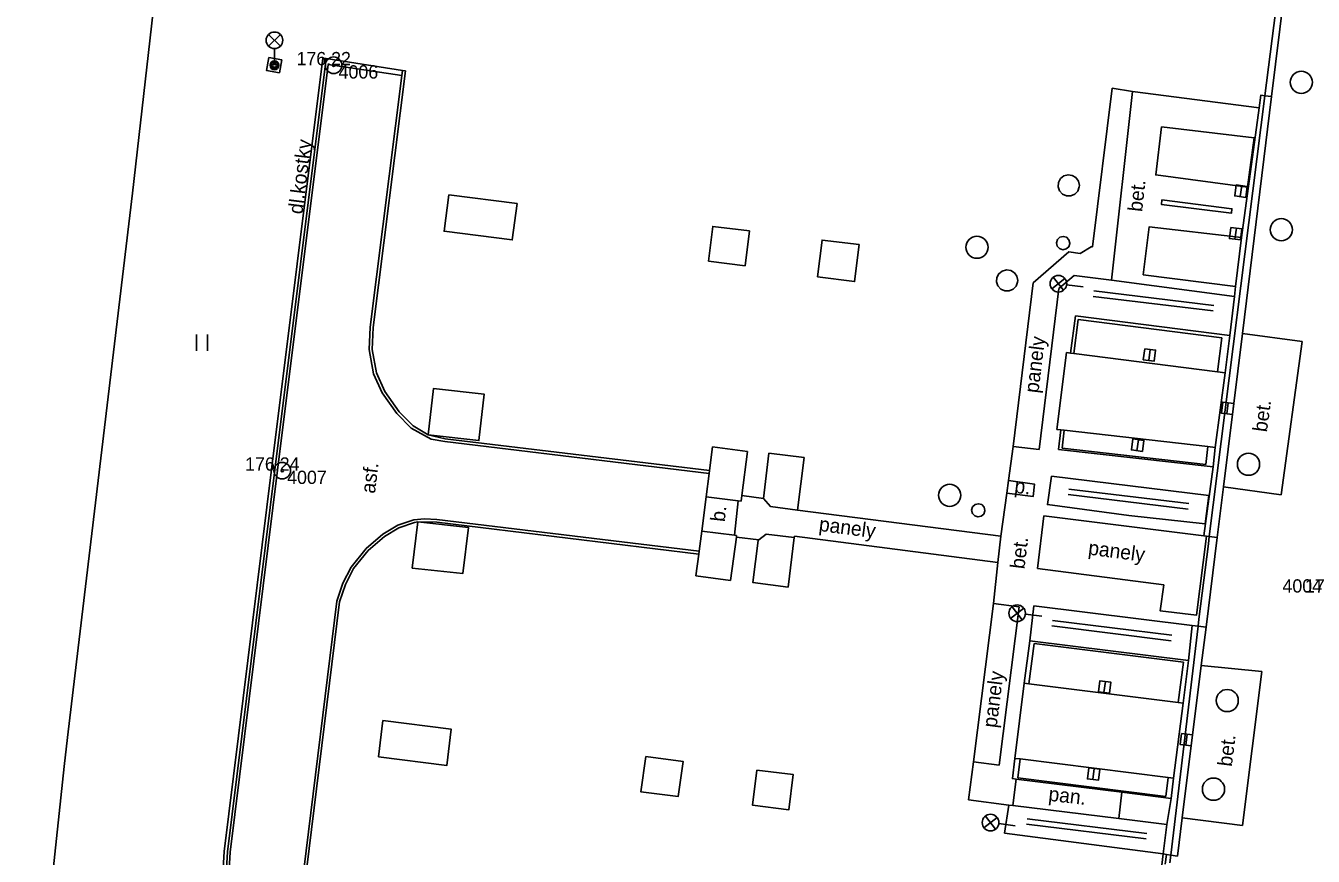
# Model space of a CAD drawing. Extents: x -540235 to -537963, y -1184915 to -1183660.
# Drawn here: x -540189.1 to -540131, y -1184039.7 to -1184002.2 of the extents above; entities that cross this region are included whole.
import ezdxf

# ---------------------------------------------------------------- set-up
doc = ezdxf.new("R2010")
doc.units = 0
for name, color, linetype in [('Vrstva 10', 7, 'Continuous'), ('Vrstva 11', 7, 'Continuous'), ('Vrstva 21', 7, 'Continuous'), ('Vrstva 22', 7, 'Continuous'), ('Vrstva 23', 7, 'Continuous'), ('Vrstva 27', 7, 'Continuous'), ('Vrstva 33', 7, 'Continuous'), ('Vrstva 36', 7, 'Continuous'), ('Vrstva 40', 7, 'Continuous'), ('Vrstva 7', 7, 'Continuous'), ('Vrstva 8', 7, 'Continuous')]:
    doc.layers.add(name, color=color, linetype=linetype)

msp = doc.modelspace()

# ---------------------------------------------------------------- linework, layer by layer
at = {"layer": 'Vrstva 10'}
for p, q in [((-540131.965, -1183998.004), (-540132.877, -1184005.381)), ((-540175.53, -1184003.67), (-540177.84, -1184022.22)), ((-540173.41, -1184015.8), (-540171.95, -1184004.22)), ((-540132.877, -1184005.381), (-540134.197, -1184016.067)), ((-540133.66, -1184007.245), (-540137.85, -1184006.755)), ((-540134.5, -1184013.955), (-540134.24, -1184011.745)), ((-540138.67, -1184013.425), (-540134.5, -1184013.955)), ((-540134.197, -1184016.067), (-540135.053, -1184022.99)), ((-540142.57, -1184020.4), (-540142.13, -1184016.93)), ((-540141.795, -1184016.973), (-540135.315, -1184017.797)), ((-540134.98, -1184017.84), (-540135.42, -1184021.21)), ((-540135.315, -1184017.797), (-540134.98, -1184017.84)), ((-540135.751, -1184021.173), (-540142.239, -1184020.437)), ((-540158.237, -1184022.253), (-540170.16, -1184020.82)), ((-540158.1, -1184021.19), (-540156.522, -1184021.393)), ((-540135.42, -1184021.21), (-540135.751, -1184021.173)), ((-540177.84, -1184022.22), (-540179.98, -1184039.46)), ((-540170.54, -1184024.59), (-540158.718, -1184026.02)), ((-540155.68, -1184025.13), (-540154.41, -1184025.28)), ((-540157.281, -1184027.211), (-540158.85, -1184027)), ((-540176.41, -1184040.28), (-540174.92, -1184028.17)), ((-540136.05, -1184031.055), (-540136.915, -1184037.929)), ((-540144.04, -1184031.85), (-540143.827, -1184031.877)), ((-540143.827, -1184031.877), (-540137.088, -1184032.723)), ((-540137.088, -1184032.723), (-540136.87, -1184032.75)), ((-540137.538, -1184036.1), (-540144.227, -1184035.268)), ((-540136.915, -1184037.929), (-540137.129, -1184039.651)), ((-540137.677, -1184040.019), (-540137.622, -1184039.573))]:
    msp.add_line(p, q, dxfattribs=at)
for points in [[(-540137.85, -1184006.755), (-540138.102, -1184008.917), (-540133.96, -1184009.475), (-540133.66, -1184007.245)], [(-540169.99, -1184009.82), (-540166.915, -1184010.214), (-540167.13, -1184011.85), (-540170.205, -1184011.456), (-540169.99, -1184009.82)], [(-540158.28, -1184012.81), (-540158.085, -1184011.242), (-540156.438, -1184011.447), (-540156.633, -1184013.014), (-540158.28, -1184012.81)], [(-540134.24, -1184011.745), (-540138.395, -1184011.256), (-540138.67, -1184013.425)], [(-540153.36, -1184013.52), (-540153.153, -1184011.854), (-540151.486, -1184012.061), (-540151.693, -1184013.727), (-540153.36, -1184013.52)], [(-540170.16, -1184020.82), (-540170.925, -1184020.636), (-540171.61, -1184020.242), (-540172.24, -1184019.6), (-540172.887, -1184018.684), (-540173.26, -1184017.85), (-540173.451, -1184016.791), (-540173.41, -1184015.8)], [(-540142.13, -1184016.93), (-540141.944, -1184016.954), (-540141.795, -1184016.973)], [(-540170.925, -1184020.636), (-540168.64, -1184020.9), (-540168.395, -1184018.814), (-540170.68, -1184018.55), (-540170.925, -1184020.636)], [(-540142.239, -1184020.437), (-540142.39, -1184020.42), (-540142.57, -1184020.4)], [(-540158.39, -1184023.44), (-540158.254, -1184022.382), (-540158.237, -1184022.253), (-540158.1, -1184021.19)], [(-540156.522, -1184021.393), (-540156.778, -1184023.379), (-540156.81, -1184023.63)], [(-540155.8, -1184023.51), (-540155.551, -1184021.477), (-540153.97, -1184021.67), (-540154.26, -1184024.04)], [(-540135.053, -1184022.99), (-540135.336, -1184025.281), (-540135.836, -1184029.323), (-540136.05, -1184031.055)], [(-540156.81, -1184023.63), (-540156.938, -1184023.615), (-540158.39, -1184023.44)], [(-540154.26, -1184024.04), (-540155.49, -1184023.87), (-540155.8, -1184023.51)], [(-540174.92, -1184028.17), (-540174.661, -1184027.39), (-540174.29, -1184026.68), (-540173.627, -1184025.855), (-540172.89, -1184025.23), (-540172.245, -1184024.84), (-540171.55, -1184024.6), (-540171.397, -1184024.575), (-540170.54, -1184024.59)], [(-540171.65, -1184026.66), (-540171.397, -1184024.575), (-540169.11, -1184024.82), (-540169.363, -1184026.905), (-540171.65, -1184026.66)], [(-540158.85, -1184027), (-540158.718, -1184026.02), (-540158.701, -1184025.891), (-540158.58, -1184024.99)], [(-540158.58, -1184024.99), (-540157.112, -1184025.177), (-540157.01, -1184025.19)], [(-540157.01, -1184025.19), (-540157.019, -1184025.259), (-540157.281, -1184027.211)], [(-540154.41, -1184025.28), (-540154.69, -1184027.51), (-540156.279, -1184027.311), (-540156.04, -1184025.41)], [(-540156.04, -1184025.41), (-540156.008, -1184025.385), (-540155.68, -1184025.13)], [(-540144.227, -1184035.268), (-540144.46, -1184035.24), (-540144.04, -1184031.85)], [(-540136.87, -1184032.75), (-540137.3, -1184036.13), (-540137.538, -1184036.1)], [(-540172.966, -1184033.531), (-540169.89, -1184033.92), (-540170.084, -1184035.559), (-540173.16, -1184035.17), (-540172.966, -1184033.531)], [(-540161.11, -1184035.16), (-540159.424, -1184035.376), (-540159.65, -1184036.96), (-540161.336, -1184036.744), (-540161.11, -1184035.16)], [(-540156.1, -1184035.77), (-540154.455, -1184035.973), (-540154.65, -1184037.56), (-540156.295, -1184037.357), (-540156.1, -1184035.77)], [(-540179.98, -1184039.46), (-540180.085, -1184041.238), (-540179.88, -1184043.51), (-540179.4, -1184045.472), (-540178.64, -1184047.36)], [(-540137.129, -1184039.651), (-540137.425, -1184039.604), (-540137.622, -1184039.573)]]:
    msp.add_lwpolyline(points, dxfattribs=at)
at = {"layer": 'Vrstva 11'}
for p, q in [((-540175.679, -1184003.651), (-540177.989, -1184022.201)), ((-540175.53, -1184003.67), (-540175.679, -1184003.651)), ((-540172.079, -1184004.204), (-540175.53, -1184003.67)), ((-540175.44, -1184003.93), (-540177.719, -1184022.235)), ((-540172.108, -1184004.43), (-540175.44, -1184003.93)), ((-540172.108, -1184004.43), (-540172.079, -1184004.204)), ((-540172.079, -1184004.204), (-540171.95, -1184004.22)), ((-540173.54, -1184015.789), (-540172.108, -1184004.43)), ((-540140.07, -1184005.01), (-540140.96, -1184012.166)), ((-540139.15, -1184005.15), (-540140.107, -1184013.667)), ((-540139.15, -1184005.15), (-540140.07, -1184005.01)), ((-540133.44, -1184005.885), (-540139.15, -1184005.15)), ((-540134.24, -1184011.745), (-540133.44, -1184005.885)), ((-540140.107, -1184013.667), (-540134.55, -1184014.395)), ((-540143.63, -1184013.78), (-540144.53, -1184021.17)), ((-540142.47, -1184014.04), (-540143.36, -1184021.31)), ((-540134.55, -1184014.395), (-540134.5, -1184013.955)), ((-540134.55, -1184014.395), (-540134.761, -1184016.159)), ((-540141.944, -1184016.954), (-540141.73, -1184015.272)), ((-540141.795, -1184016.973), (-540141.6, -1184015.44)), ((-540141.73, -1184015.272), (-540134.761, -1184016.159)), ((-540141.6, -1184015.44), (-540135.12, -1184016.265)), ((-540135.12, -1184016.265), (-540135.315, -1184017.797)), ((-540134.761, -1184016.159), (-540134.98, -1184017.84)), ((-540131.5, -1184016.435), (-540134.197, -1184016.067)), ((-540132.45, -1184023.345), (-540131.5, -1184016.435)), ((-540142.39, -1184020.42), (-540142.49, -1184021.3)), ((-540142.239, -1184020.437), (-540142.33, -1184021.24)), ((-540158.254, -1184022.382), (-540170.179, -1184020.949)), ((-540144.74, -1184022.71), (-540144.53, -1184021.17)), ((-540143.36, -1184021.31), (-540144.53, -1184021.17)), ((-540142.33, -1184021.24), (-540135.842, -1184021.975)), ((-540135.842, -1184021.975), (-540135.751, -1184021.173)), ((-540135.52, -1184022.09), (-540135.42, -1184021.21)), ((-540142.49, -1184021.3), (-540135.52, -1184022.09)), ((-540177.989, -1184022.201), (-540180.129, -1184039.446)), ((-540177.719, -1184022.235), (-540179.859, -1184039.471)), ((-540135.52, -1184022.09), (-540135.929, -1184025.206)), ((-540142.81, -1184022.51), (-540135.713, -1184023.374)), ((-540135.053, -1184022.99), (-540132.45, -1184023.345)), ((-540158.39, -1184023.44), (-540158.58, -1184024.99)), ((-540155.8, -1184023.51), (-540156.778, -1184023.379)), ((-540135.713, -1184023.374), (-540135.87, -1184024.66)), ((-540156.938, -1184023.615), (-540157.112, -1184025.177)), ((-540154.26, -1184024.04), (-540145.1, -1184025.22)), ((-540170.528, -1184024.46), (-540158.701, -1184025.891)), ((-540143.44, -1184026.67), (-540143.15, -1184024.3)), ((-540143.15, -1184024.3), (-540135.929, -1184025.206)), ((-540156.008, -1184025.385), (-540157.019, -1184025.259)), ((-540154.403, -1184025.222), (-540154.41, -1184025.28)), ((-540145.23, -1184026.41), (-540154.403, -1184025.222)), ((-540135.929, -1184025.206), (-540135.82, -1184025.22)), ((-540137.74, -1184027.41), (-540143.44, -1184026.67)), ((-540176.54, -1184040.27), (-540175.047, -1184028.141)), ((-540146.33, -1184035.4), (-540145.43, -1184028.25)), ((-540145.43, -1184028.25), (-540144.27, -1184028.41)), ((-540144.27, -1184028.41), (-540145.17, -1184035.55)), ((-540143.6, -1184028.36), (-540143.79, -1184029.93)), ((-540136.46, -1184029.25), (-540143.6, -1184028.36)), ((-540136.625, -1184030.826), (-540136.46, -1184029.25)), ((-540144.04, -1184031.85), (-540143.79, -1184029.93)), ((-540143.79, -1184029.93), (-540136.625, -1184030.826)), ((-540143.827, -1184031.877), (-540143.59, -1184030.06)), ((-540143.59, -1184030.06), (-540136.857, -1184030.902)), ((-540136.857, -1184030.902), (-540137.088, -1184032.723)), ((-540136.625, -1184030.826), (-540136.87, -1184032.75)), ((-540133.318, -1184031.324), (-540136.05, -1184031.055)), ((-540134.184, -1184038.27), (-540133.318, -1184031.324)), ((-540145.17, -1184035.55), (-540146.33, -1184035.4)), ((-540144.227, -1184035.268), (-540144.33, -1184036.12)), ((-540144.398, -1184036.172), (-540144.55, -1184037.372)), ((-540144.33, -1184036.12), (-540137.647, -1184036.954)), ((-540137.647, -1184036.954), (-540137.538, -1184036.1)), ((-540139.631, -1184036.766), (-540139.768, -1184037.959)), ((-540144.92, -1184038.62), (-540144.73, -1184037.35)), ((-540136.915, -1184037.929), (-540134.184, -1184038.27)), ((-540137.77, -1184039.55), (-540144.92, -1184038.62)), ((-540137.833, -1184040.063), (-540137.77, -1184039.55)), ((-540137.77, -1184039.55), (-540137.622, -1184039.573))]:
    msp.add_line(p, q, dxfattribs=at)
for points in [[(-540178.11, -1184003.62), (-540177.53, -1184003.73), (-540177.64, -1184004.31), (-540178.22, -1184004.2), (-540178.11, -1184003.62)], [(-540132.877, -1184005.381), (-540133.18, -1184005.343), (-540133.366, -1184005.32), (-540133.44, -1184005.885)], [(-540141.55, -1184009.39), (-540141.59, -1184009.199), (-540141.702, -1184009.04), (-540141.868, -1184008.938), (-540142.061, -1184008.911), (-540142.249, -1184008.963), (-540142.401, -1184009.085), (-540142.491, -1184009.258), (-540142.506, -1184009.452), (-540142.442, -1184009.636), (-540142.31, -1184009.78), (-540142.132, -1184009.859), (-540141.937, -1184009.861), (-540141.757, -1184009.785), (-540141.623, -1184009.644), (-540141.555, -1184009.461), (-540141.55, -1184009.39)], [(-540141.98, -1184011.99), (-540142.019, -1184011.841), (-540142.127, -1184011.732), (-540142.275, -1184011.69), (-540142.424, -1184011.727), (-540142.535, -1184011.833), (-540142.58, -1184011.98), (-540142.546, -1184012.129), (-540142.442, -1184012.243), (-540142.296, -1184012.29), (-540142.145, -1184012.258), (-540142.03, -1184012.156), (-540141.981, -1184012.011), (-540141.98, -1184011.99)], [(-540140.96, -1184012.166), (-540141.01, -1184012.16), (-540141.51, -1184012.46), (-540142.02, -1184012.39), (-540143.63, -1184013.78)], [(-540144.33, -1184013.68), (-540144.37, -1184013.489), (-540144.482, -1184013.33), (-540144.648, -1184013.228), (-540144.841, -1184013.201), (-540145.029, -1184013.253), (-540145.181, -1184013.375), (-540145.271, -1184013.548), (-540145.286, -1184013.742), (-540145.222, -1184013.926), (-540145.09, -1184014.07), (-540144.912, -1184014.149), (-540144.717, -1184014.151), (-540144.537, -1184014.075), (-540144.403, -1184013.934), (-540144.335, -1184013.751), (-540144.33, -1184013.68)], [(-540140.107, -1184013.667), (-540141.78, -1184013.46), (-540142.47, -1184014.04)], [(-540170.179, -1184020.949), (-540170.794, -1184020.844), (-540171.69, -1184020.346), (-540172.34, -1184019.684), (-540173, -1184018.749), (-540173.385, -1184017.889), (-540173.581, -1184016.8), (-540173.54, -1184015.789)], [(-540144.74, -1184022.71), (-540143.57, -1184022.87), (-540143.64, -1184023.43), (-540144.82, -1184023.28), (-540144.74, -1184022.71)], [(-540135.87, -1184024.66), (-540139.32, -1184024.29), (-540142.99, -1184023.79), (-540142.81, -1184022.51)], [(-540145.43, -1184028.25), (-540145.23, -1184026.41), (-540145.1, -1184025.22), (-540144.82, -1184023.28)], [(-540145.81, -1184024.05), (-540145.849, -1184023.901), (-540145.957, -1184023.792), (-540146.105, -1184023.75), (-540146.254, -1184023.787), (-540146.365, -1184023.893), (-540146.41, -1184024.04), (-540146.376, -1184024.189), (-540146.272, -1184024.303), (-540146.126, -1184024.35), (-540145.975, -1184024.318), (-540145.86, -1184024.216), (-540145.811, -1184024.071), (-540145.81, -1184024.05)], [(-540175.047, -1184028.141), (-540174.782, -1184027.339), (-540174.399, -1184026.608), (-540173.72, -1184025.764), (-540172.966, -1184025.124), (-540172.301, -1184024.721), (-540171.578, -1184024.472), (-540171.098, -1184024.426), (-540170.528, -1184024.46)], [(-540135.82, -1184025.22), (-540136.27, -1184028.78), (-540137.9, -1184028.59), (-540137.74, -1184027.41)], [(-540135.336, -1184025.281), (-540135.689, -1184025.237), (-540135.82, -1184025.22)], [(-540135.836, -1184029.323), (-540136.198, -1184029.281), (-540136.46, -1184029.25)], [(-540144.73, -1184037.35), (-540146.55, -1184037.11), (-540146.33, -1184035.4)], [(-540144.46, -1184035.24), (-540144.57, -1184036.15), (-540144.398, -1184036.172), (-540139.631, -1184036.766), (-540137.416, -1184037.043), (-540137.3, -1184036.13)], [(-540144.73, -1184037.35), (-540144.55, -1184037.372), (-540139.768, -1184037.959), (-540137.607, -1184038.223)], [(-540137.416, -1184037.043), (-540137.607, -1184038.223), (-540137.77, -1184039.55)], [(-540180.129, -1184039.446), (-540180.235, -1184041.24), (-540180.028, -1184043.535), (-540179.543, -1184045.518), (-540178.775, -1184047.427)], [(-540179.859, -1184039.471), (-540179.963, -1184041.236), (-540179.76, -1184043.49), (-540179.284, -1184045.435), (-540178.531, -1184047.306)]]:
    msp.add_lwpolyline(points, dxfattribs=at)
at = {"layer": 'Vrstva 21'}
for centre, radius in [((-540175.19, -1184003.97), 0.375), ((-540175.19, -1184003.97), 0.05), ((-540177.51, -1184022.26), 0.375), ((-540177.51, -1184022.26), 0.05)]:
    msp.add_circle(centre, radius, dxfattribs=at)
at = {"layer": 'Vrstva 27'}
for p, q in [((-540134.292, -1184009.898), (-540134.228, -1184009.402)), ((-540134.532, -1184011.818), (-540134.468, -1184011.322)), ((-540138.356, -1184016.79), (-540138.42, -1184017.286)), ((-540134.897, -1184019.692), (-540134.837, -1184019.196)), ((-540138.952, -1184021.358), (-540138.888, -1184020.862)), ((-540140.442, -1184032.268), (-540140.378, -1184031.772)), ((-540136.752, -1184034.649), (-540136.692, -1184034.153)), ((-540140.879, -1184035.702), (-540140.941, -1184036.198))]:
    msp.add_line(p, q, dxfattribs=at)
for points in [[(-540134.044, -1184009.93), (-540133.98, -1184009.434), (-540134.476, -1184009.37), (-540134.54, -1184009.866)], [(-540134.284, -1184011.85), (-540134.22, -1184011.354), (-540134.716, -1184011.29), (-540134.78, -1184011.786)], [(-540138.604, -1184016.758), (-540138.668, -1184017.254), (-540138.172, -1184017.318), (-540138.108, -1184016.822)], [(-540134.649, -1184019.722), (-540134.589, -1184019.226), (-540135.085, -1184019.166), (-540135.145, -1184019.662)], [(-540138.704, -1184021.39), (-540138.64, -1184020.894), (-540139.136, -1184020.83), (-540139.2, -1184021.326)], [(-540140.194, -1184032.3), (-540140.13, -1184031.804), (-540140.626, -1184031.74), (-540140.69, -1184032.236)], [(-540136.504, -1184034.679), (-540136.444, -1184034.183), (-540136.94, -1184034.123), (-540137, -1184034.619)], [(-540141.127, -1184035.671), (-540141.189, -1184036.167), (-540140.693, -1184036.229), (-540140.631, -1184035.733)]]:
    msp.add_lwpolyline(points, close=True, dxfattribs=at)
for centre in [(-540131.54, -1184004.74), (-540132.44, -1184011.39), (-540146.17, -1184012.18), (-540133.92, -1184021.97), (-540147.4, -1184023.37), (-540134.88, -1184032.63), (-540135.5, -1184036.63)]:
    msp.add_circle(centre, 0.5, dxfattribs=at)
at = {"layer": 'Vrstva 33'}
for p, q in [((-540178.125, -1184003.11), (-540177.595, -1184002.58)), ((-540178.125, -1184002.58), (-540177.595, -1184003.11)), ((-540177.86, -1184003.22), (-540177.86, -1184003.97)), ((-540142.792, -1184014.058), (-540142.201, -1184013.596)), ((-540142.266, -1184014.122), (-540142.727, -1184013.532)), ((-540142.124, -1184013.873), (-540141.38, -1184013.964)), ((-540144.652, -1184028.924), (-540144.061, -1184028.462)), ((-540144.126, -1184028.988), (-540144.587, -1184028.398)), ((-540143.984, -1184028.739), (-540143.24, -1184028.83)), ((-540145.853, -1184038.37), (-540145.262, -1184037.908)), ((-540145.327, -1184038.434), (-540145.788, -1184037.844)), ((-540145.185, -1184038.185), (-540144.441, -1184038.276))]:
    msp.add_line(p, q, dxfattribs=at)
for centre, radius in [((-540177.86, -1184002.845), 0.375), ((-540177.86, -1184003.97), 0.2), ((-540177.86, -1184003.97), 0.1445), ((-540177.86, -1184003.97), 0.0876), ((-540142.4966, -1184013.8271), 0.375), ((-540144.3566, -1184028.6931), 0.375), ((-540145.5576, -1184038.1391), 0.375)]:
    msp.add_circle(centre, radius, dxfattribs=at)
at = {"layer": 'Vrstva 36'}
for p, q in [((-540181.377, -1184016.86), (-540181.377, -1184016.11)), ((-540180.877, -1184016.86), (-540180.877, -1184016.11))]:
    msp.add_line(p, q, dxfattribs=at)
at = {"layer": 'Vrstva 7'}
for p, q in [((-540184.259, -1184009.742), (-540182.429, -1183993.61)), ((-540132.551, -1184000.353), (-540133.18, -1184005.343)), ((-540133.18, -1184005.343), (-540135.689, -1184025.237)), ((-540186.789, -1184030.891), (-540184.259, -1184009.742)), ((-540135.481, -1184014.807), (-540140.898, -1184014.148)), ((-540135.511, -1184015.056), (-540140.929, -1184014.396)), ((-540136.641, -1184023.996), (-540142.059, -1184023.336)), ((-540136.611, -1184023.747), (-540142.028, -1184023.088)), ((-540135.689, -1184025.237), (-540135.73, -1184025.565)), ((-540137.412, -1184029.931), (-540142.79, -1184029.264)), ((-540137.382, -1184029.683), (-540142.759, -1184029.016)), ((-540136.198, -1184029.281), (-540137.425, -1184039.604)), ((-540136.16, -1184028.965), (-540136.198, -1184029.281)), ((-540187.192, -1184034.3), (-540186.789, -1184030.891)), ((-540189.08, -1184052.04), (-540187.346, -1184035.611)), ((-540138.501, -1184038.627), (-540143.899, -1184037.965)), ((-540138.531, -1184038.875), (-540143.929, -1184038.213)), ((-540137.425, -1184039.604), (-540137.467, -1184039.959))]:
    msp.add_line(p, q, dxfattribs=at)
msp.add_lwpolyline([(-540137.825, -1184010.046), (-540134.665, -1184010.446), (-540134.69, -1184010.645), (-540137.85, -1184010.245), (-540137.825, -1184010.046)], dxfattribs=at)
at = {"layer": 'Vrstva 8'}
for p, q in [((-540136.16, -1184028.965), (-540135.73, -1184025.565)), ((-540187.346, -1184035.611), (-540187.192, -1184034.3))]:
    msp.add_line(p, q, dxfattribs=at)

# ---------------------------------------------------------------- texts
at = {"layer": 'Vrstva 22'}
for s, p in [('176.22', (-540176.865, -1184003.97)), ('176.24', (-540179.185, -1184022.26)), ('176.11', (-540131.37, -1184027.76))]:
    msp.add_text(s, height=0.6, dxfattribs=at).set_placement(p)
at = {"layer": 'Vrstva 23'}
for s, p in [(' 4006', (-540175.19, -1184004.57)), (' 4007', (-540177.51, -1184022.86)), ('4004 ', (-540132.387, -1184027.76))]:
    msp.add_text(s, height=0.6, dxfattribs=at).set_placement(p)
at = {"layer": 'Vrstva 40'}
for s, rotation, p in [('dl.kostky', 82.901592, (-540176.6, -1184010.712)), ('bet.', 83.588936, (-540138.721, -1184010.603)), ('panely', 83.020525, (-540143.399, -1184018.782)), ('bet.', 82.171942, (-540133.092, -1184020.544)), ('asf.', 82.901592, (-540173.33, -1184023.314)), ('p.', 352.755492, (-540144.505, -1184023.253)), ('b.', 83.659808, (-540157.55, -1184024.591)), ('panely', 352.621006, (-540153.325, -1184024.976)), ('bet.', 83.023803, (-540144.031, -1184026.72)), ('panely', 352.621006, (-540141.176, -1184026.043)), ('panely', 82.815733, (-540145.285, -1184033.884)), ('bet.', 82.893256, (-540134.673, -1184035.634)), ('pan.', 353.480197, (-540142.967, -1184037.15))]:
    msp.add_text(s, height=0.65, rotation=rotation, dxfattribs=at).set_placement(p)

doc.saveas('drawing.dxf')
